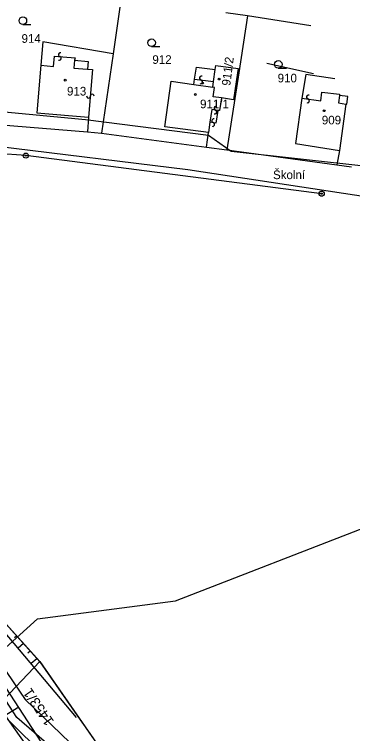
# Model space of a CAD drawing. Extents: x -469926 to -462499, y -1098642 to -1092733.
# Drawn here: x -465657.2 to -465590.7, y -1094686.3 to -1094544.8 of the extents above; entities that cross this region are included whole.
import ezdxf

# ---------------------------------------------------------------- set-up
doc = ezdxf.new("R2010")
doc.units = 0
for name, color, linetype in [('Vrstva 1', 7, 'Continuous'), ('Vrstva 10', 7, 'Continuous'), ('Vrstva 12', 7, 'Continuous'), ('Vrstva 14', 7, 'Continuous'), ('Vrstva 24', 7, 'Continuous'), ('Vrstva 25', 7, 'Continuous'), ('Vrstva 4', 7, 'Continuous'), ('Vrstva 48', 7, 'Continuous'), ('Vrstva 50', 7, 'Continuous'), ('Vrstva 51', 7, 'Continuous'), ('Vrstva 6', 7, 'Continuous'), ('Vrstva 63', 7, 'Continuous'), ('Vrstva 8', 7, 'Continuous')]:
    doc.layers.add(name, color=color, linetype=linetype)

msp = doc.modelspace()

# ---------------------------------------------------------------- linework, layer by layer
at = {"layer": 'Vrstva 1'}
for p, q in [((-465636.16, -1094541.5), (-465637.77, -1094552.57)), ((-465636.16, -1094541.5), (-465637.77, -1094552.57)), ((-465611.32, -1094545.13), (-465615.57, -1094544.51)), ((-465611.32, -1094545.13), (-465615.57, -1094544.51)), ((-465611.32, -1094545.13), (-465613.04, -1094556.33)), ((-465611.32, -1094545.13), (-465613.04, -1094556.33)), ((-465598.88, -1094547.04), (-465611.32, -1094545.13)), ((-465598.88, -1094547.04), (-465611.32, -1094545.13)), ((-465651.57, -1094550.2), (-465651.99, -1094554.83)), ((-465651.57, -1094550.2), (-465651.99, -1094554.83)), ((-465637.77, -1094552.57), (-465651.57, -1094550.2)), ((-465637.77, -1094552.57), (-465651.57, -1094550.2)), ((-465637.77, -1094552.57), (-465640.03, -1094568.16)), ((-465637.77, -1094552.57), (-465640.03, -1094568.16)), ((-465651.99, -1094554.83), (-465652.73, -1094564.21)), ((-465651.99, -1094554.83), (-465652.73, -1094564.21)), ((-465617.66, -1094555.69), (-465617.54, -1094554.85)), ((-465617.66, -1094555.69), (-465617.54, -1094554.85)), ((-465617.54, -1094554.85), (-465613.16, -1094555.49)), ((-465617.54, -1094554.85), (-465613.16, -1094555.49)), ((-465607.54, -1094554.4), (-465598.34, -1094556.44)), ((-465607.54, -1094554.4), (-465598.34, -1094556.44)), ((-465621.77, -1094557.56), (-465621.38, -1094555.18)), ((-465621.77, -1094557.56), (-465621.38, -1094555.18)), ((-465621.38, -1094555.18), (-465617.66, -1094555.69)), ((-465621.38, -1094555.18), (-465617.66, -1094555.69)), ((-465618, -1094558.02), (-465617.66, -1094555.69)), ((-465618, -1094558.02), (-465617.66, -1094555.69)), ((-465613.04, -1094556.33), (-465615.37, -1094571.49)), ((-465613.04, -1094556.33), (-465615.37, -1094571.49)), ((-465613.28, -1094556.3), (-465614.06, -1094561.65)), ((-465613.28, -1094556.3), (-465614.06, -1094561.65)), ((-465613.16, -1094555.49), (-465613.28, -1094556.3)), ((-465613.16, -1094555.49), (-465613.28, -1094556.3)), ((-465613.28, -1094556.3), (-465613.04, -1094556.33)), ((-465613.28, -1094556.3), (-465613.04, -1094556.33)), ((-465621.91, -1094558.59), (-465621.77, -1094557.56)), ((-465621.91, -1094558.59), (-465621.77, -1094557.56)), ((-465599.83, -1094556.66), (-465600.65, -1094561.28)), ((-465594.17, -1094557.49), (-465599.83, -1094556.66)), ((-465627.59, -1094566.91), (-465626.37, -1094557.95)), ((-465627.59, -1094566.91), (-465626.37, -1094557.95)), ((-465626.37, -1094557.95), (-465621.91, -1094558.59)), ((-465626.37, -1094557.95), (-465621.91, -1094558.59)), ((-465618.16, -1094559.14), (-465618, -1094558.02)), ((-465618.16, -1094559.14), (-465618, -1094558.02)), ((-465617.82, -1094559.19), (-465618.16, -1094559.14)), ((-465617.82, -1094559.19), (-465618.16, -1094559.14)), ((-465618.06, -1094561.01), (-465617.82, -1094559.19)), ((-465618.06, -1094561.01), (-465617.82, -1094559.19)), ((-465616.46, -1094561.21), (-465618.06, -1094561.01)), ((-465616.46, -1094561.21), (-465618.06, -1094561.01)), ((-465614.06, -1094561.65), (-465616.46, -1094561.21)), ((-465614.06, -1094561.65), (-465616.46, -1094561.21)), ((-465600.65, -1094561.28), (-465601.91, -1094570.19)), ((-465652.73, -1094564.21), (-465642.57, -1094565.03)), ((-465652.73, -1094564.21), (-465642.57, -1094565.03)), ((-465663.66, -1094566.23), (-465642.79, -1094567.93)), ((-465663.66, -1094566.23), (-465642.79, -1094567.93)), ((-465642.57, -1094565.03), (-465642.79, -1094567.93)), ((-465642.57, -1094565.03), (-465642.79, -1094567.93)), ((-465618.98, -1094568.05), (-465627.59, -1094566.91)), ((-465618.98, -1094568.05), (-465627.59, -1094566.91)), ((-465654.92, -1094572.6), (-465713, -1094568.41)), ((-465654.92, -1094572.6), (-465713, -1094568.41)), ((-465642.79, -1094567.93), (-465640.03, -1094568.16)), ((-465642.79, -1094567.93), (-465640.03, -1094568.16)), ((-465640.03, -1094568.16), (-465619.38, -1094570.95)), ((-465640.03, -1094568.16), (-465619.38, -1094570.95)), ((-465619.38, -1094570.95), (-465618.98, -1094568.05)), ((-465619.38, -1094570.95), (-465618.98, -1094568.05)), ((-465601.91, -1094570.19), (-465593.22, -1094571.59)), ((-465619.38, -1094570.95), (-465615.37, -1094571.49)), ((-465619.38, -1094570.95), (-465615.37, -1094571.49)), ((-465615.37, -1094571.49), (-465593.75, -1094574.44)), ((-465593.22, -1094571.59), (-465593.75, -1094574.44)), ((-465596.74, -1094580.09), (-465654.92, -1094572.6)), ((-465593.75, -1094574.44), (-465590.86, -1094574.83)), ((-465660.01, -1094663.44), (-465652.18, -1094672.09)), ((-465660.01, -1094663.44), (-465652.18, -1094672.09)), ((-465652.18, -1094672.09), (-465617.16, -1094722.6))]:
    msp.add_line(p, q, dxfattribs=at)
at = {"layer": 'Vrstva 10'}
msp.add_lwpolyline([(-465713, -1094568.41), (-465707.97, -1094574.94), (-465696.43, -1094593.1), (-465670.01, -1094647.6), (-465660.01, -1094663.44), (-465652.18, -1094672.09), (-465617.16, -1094722.6)], dxfattribs=at)
at = {"layer": 'Vrstva 12'}
for p, q in [((-465625.5, -1094660.17), (-465579.71, -1094642.44)), ((-465652.64, -1094663.73), (-465625.5, -1094660.17)), ((-465652.64, -1094663.73), (-465625.5, -1094660.17)), ((-465660.37, -1094670.68), (-465652.64, -1094663.73)), ((-465660.37, -1094670.68), (-465652.64, -1094663.73))]:
    msp.add_line(p, q, dxfattribs=at)
at = {"layer": 'Vrstva 14'}
for p, q in [((-465643.21, -1094565.55), (-465675.65, -1094562.56)), ((-465643.21, -1094565.55), (-465675.65, -1094562.56)), ((-465619.02, -1094568.67), (-465643.21, -1094565.55)), ((-465619.02, -1094568.67), (-465643.21, -1094565.55)), ((-465614.52, -1094571.79), (-465619.02, -1094568.67)), ((-465614.52, -1094571.79), (-465619.02, -1094568.67)), ((-465561.31, -1094577.68), (-465614.52, -1094571.79))]:
    msp.add_line(p, q, dxfattribs=at)
at = {"layer": 'Vrstva 24'}
for centre, radius in [((-465654.92, -1094572.6), 0.5), ((-465654.92, -1094572.6), 0.5), ((-465654.92, -1094572.6), 0.1), ((-465654.92, -1094572.6), 0.1), ((-465596.74, -1094580.09), 0.5), ((-465596.74, -1094580.09), 0.1)]:
    msp.add_circle(centre, radius, dxfattribs=at)
at = {"layer": 'Vrstva 25'}
for p, q in [((-465655.51, -1094546.81), (-465653.91, -1094546.81)), ((-465655.51, -1094546.81), (-465653.91, -1094546.81)), ((-465630.19, -1094551.14), (-465628.59, -1094551.14)), ((-465630.19, -1094551.14), (-465628.59, -1094551.14)), ((-465605.28, -1094555.41), (-465603.68, -1094555.41)), ((-465605.28, -1094555.41), (-465603.68, -1094555.41))]:
    msp.add_line(p, q, dxfattribs=at)
for centre, radius in [((-465655.51, -1094546.06), 0.75), ((-465655.51, -1094546.06), 0.75), ((-465630.19, -1094550.39), 0.75), ((-465630.19, -1094550.39), 0.75), ((-465605.28, -1094554.66), 0.75), ((-465605.28, -1094554.66), 0.75), ((-465647.17, -1094557.77), 0.175), ((-465647.17, -1094557.77), 0.175), ((-465616.9, -1094557.54), 0.175), ((-465616.9, -1094557.54), 0.175), ((-465620.15, -1094558.33), 0.175), ((-465620.15, -1094558.33), 0.175), ((-465621.59, -1094560.58), 0.175), ((-465621.59, -1094560.58), 0.175), ((-465596.24, -1094563.78), 0.175)]:
    msp.add_circle(centre, radius, dxfattribs=at)
at = {"layer": 'Vrstva 4'}
for p, q in [((-465649.48, -1094555.07), (-465649.26, -1094553.02)), ((-465649.48, -1094555.07), (-465649.26, -1094553.02)), ((-465649.26, -1094553.02), (-465645.25, -1094553.37)), ((-465649.26, -1094553.02), (-465645.25, -1094553.37)), ((-465645.25, -1094553.37), (-465645.35, -1094553.84)), ((-465645.25, -1094553.37), (-465645.35, -1094553.84)), ((-465651.99, -1094554.83), (-465649.48, -1094555.07)), ((-465651.99, -1094554.83), (-465649.48, -1094555.07)), ((-465645.35, -1094553.84), (-465645.47, -1094555.37)), ((-465645.35, -1094553.84), (-465645.47, -1094555.37)), ((-465645.35, -1094553.84), (-465642.67, -1094554.06)), ((-465645.35, -1094553.84), (-465642.67, -1094554.06)), ((-465642.67, -1094554.06), (-465642.79, -1094555.59)), ((-465642.67, -1094554.06), (-465642.79, -1094555.59)), ((-465645.47, -1094555.37), (-465642.79, -1094555.59)), ((-465645.47, -1094555.37), (-465642.79, -1094555.59)), ((-465642.79, -1094555.59), (-465641.81, -1094555.67)), ((-465642.79, -1094555.59), (-465641.81, -1094555.67)), ((-465641.81, -1094555.67), (-465642.57, -1094565.03)), ((-465641.81, -1094555.67), (-465642.57, -1094565.03)), ((-465621.77, -1094557.56), (-465618, -1094558.02)), ((-465621.77, -1094557.56), (-465618, -1094558.02)), ((-465621.91, -1094558.59), (-465618.16, -1094559.14)), ((-465621.91, -1094558.59), (-465618.16, -1094559.14)), ((-465596.93, -1094561.82), (-465596.71, -1094560.09)), ((-465596.71, -1094560.09), (-465593.23, -1094560.53)), ((-465593.23, -1094560.53), (-465593.26, -1094560.79)), ((-465616.46, -1094561.21), (-465616.85, -1094563.73)), ((-465616.46, -1094561.21), (-465616.85, -1094563.73)), ((-465600.65, -1094561.28), (-465596.93, -1094561.82)), ((-465593.26, -1094560.79), (-465593.46, -1094562.25)), ((-465591.61, -1094561), (-465593.26, -1094560.79)), ((-465591.81, -1094562.5), (-465591.61, -1094561)), ((-465593.46, -1094562.25), (-465591.98, -1094562.51)), ((-465591.98, -1094562.51), (-465593.22, -1094571.59)), ((-465591.98, -1094562.51), (-465591.81, -1094562.5)), ((-465618.37, -1094563.55), (-465618.71, -1094566.03)), ((-465618.37, -1094563.55), (-465618.71, -1094566.03)), ((-465617.19, -1094563.71), (-465618.37, -1094563.55)), ((-465617.19, -1094563.71), (-465618.37, -1094563.55)), ((-465617.19, -1094563.71), (-465617.53, -1094566.19)), ((-465617.19, -1094563.71), (-465617.53, -1094566.19)), ((-465616.85, -1094563.73), (-465617.19, -1094563.71)), ((-465616.85, -1094563.73), (-465617.19, -1094563.71)), ((-465618.71, -1094566.03), (-465618.98, -1094568.05)), ((-465618.71, -1094566.03), (-465618.98, -1094568.05)), ((-465617.53, -1094566.19), (-465618.71, -1094566.03)), ((-465617.53, -1094566.19), (-465618.71, -1094566.03)), ((-465670.79, -1094691.66), (-465652.18, -1094672.09)), ((-465670.79, -1094691.66), (-465652.18, -1094672.09))]:
    msp.add_line(p, q, dxfattribs=at)
at = {"layer": 'Vrstva 48'}
for points in [[(-465656.72, -1094667.08), (-465657.17, -1094667.49)], [(-465656.72, -1094667.08), (-465657.17, -1094667.49)], [(-465655.39, -1094668.58), (-465656.43, -1094669.5)], [(-465655.39, -1094668.58), (-465656.43, -1094669.5)], [(-465654.06, -1094670.07), (-465654.54, -1094670.5)], [(-465654.06, -1094670.07), (-465654.54, -1094670.5)], [(-465652.74, -1094671.57), (-465653.85, -1094672.54)], [(-465652.74, -1094671.57), (-465653.85, -1094672.54)], [(-465659.48, -1094683), (-465656.33, -1094681.02)], [(-465659.48, -1094683), (-465656.33, -1094681.02)]]:
    msp.add_lwpolyline(points, dxfattribs=at)
at = {"layer": 'Vrstva 51'}
for centre, radius, start, end in [((-465648.15, -1094552.74), 0.376, 68.9904, 255.3015), ((-465648.15, -1094552.74), 0.376, 68.9904, 255.3015), ((-465648.34, -1094553.47), 0.377, 248.3143, 75.9775), ((-465648.34, -1094553.47), 0.377, 248.3143, 75.9775), ((-465620.38, -1094557.35), 0.376, 68.9904, 255.3015), ((-465620.38, -1094557.35), 0.376, 68.9904, 255.3015), ((-465620.56, -1094558.08), 0.377, 248.3143, 75.9775), ((-465620.56, -1094558.08), 0.377, 248.3143, 75.9775), ((-465641.86, -1094560.89), 0.376, 354.7104, 181.0215), ((-465641.86, -1094560.89), 0.376, 354.7104, 181.0215), ((-465642.61, -1094560.9), 0.377, 174.0343, 1.6975), ((-465642.61, -1094560.9), 0.377, 174.0343, 1.6975), ((-465599.35, -1094561.09), 0.376, 68.9904, 255.3015), ((-465599.53, -1094561.82), 0.377, 248.3143, 75.9775), ((-465617.55, -1094563.28), 0.376, 68.9904, 255.3015), ((-465617.55, -1094563.28), 0.376, 68.9904, 255.3015), ((-465617.74, -1094564.01), 0.377, 248.3143, 75.9775), ((-465617.74, -1094564.01), 0.377, 248.3143, 75.9775), ((-465617.99, -1094565.75), 0.376, 68.9904, 255.3015), ((-465617.99, -1094565.75), 0.376, 68.9904, 255.3015), ((-465618.17, -1094566.48), 0.377, 248.3143, 75.9775), ((-465618.17, -1094566.48), 0.377, 248.3143, 75.9775)]:
    msp.add_arc(centre, radius, start, end, dxfattribs=at)
at = {"layer": 'Vrstva 6'}
for points in [[(-465764.57, -1094524.1), (-465744.54, -1094553.15), (-465728.17, -1094576.48), (-465711.62, -1094600.56), (-465689.57, -1094631.93), (-465682.97, -1094643.74), (-465676.37, -1094655.54), (-465658.45, -1094683.55), (-465643.77, -1094704.26), (-465629.83, -1094723.97), (-465615.89, -1094743.67), (-465598.7, -1094758.84), (-465586.6, -1094780.28), (-465568.25, -1094802.77), (-465557.01, -1094824.5), (-465549.26, -1094833.47), (-465549.2, -1094829.81)], [(-465711.62, -1094600.56), (-465688.58, -1094629.09), (-465673.68, -1094652.27), (-465655.08, -1094679.58), (-465632.16, -1094701.61), (-465626.96, -1094703.6)], [(-465628.68, -1094705.89), (-465635.69, -1094701.33), (-465656.72, -1094683.11), (-465675.29, -1094654.47), (-465681.87, -1094645.7)], [(-465658.45, -1094683.55), (-465636.49, -1094705.33), (-465630.25, -1094708.75)]]:
    msp.add_lwpolyline(points, dxfattribs=at)
at = {"layer": 'Vrstva 63'}
for points in [[(-465643.79, -1094700.32), (-465644.09, -1094699.91), (-465689.14, -1094630.72)], [(-465644.93, -1094683.17), (-465689.14, -1094630.72)], [(-465643.79, -1094700.32), (-465644.09, -1094699.91), (-465689.14, -1094630.72)], [(-465644.93, -1094683.17), (-465689.14, -1094630.72)], [(-465660, -1094663.46), (-465652.18, -1094672.2)], [(-465660, -1094663.46), (-465652.18, -1094672.2)], [(-465652.18, -1094672.2), (-465643.79, -1094684.28)], [(-465652.18, -1094672.2), (-465643.79, -1094684.28)]]:
    msp.add_lwpolyline(points, dxfattribs=at)
at = {"layer": 'Vrstva 8'}
for p, q in [((-465623.08, -1094575.43), (-465672.04, -1094569.38)), ((-465623.08, -1094575.43), (-465672.04, -1094569.38)), ((-465538.56, -1094588.22), (-465623.08, -1094575.43))]:
    msp.add_line(p, q, dxfattribs=at)

# ---------------------------------------------------------------- texts
at = {"layer": 'Vrstva 50'}
for s, p in [('914', (-465655.77, -1094550.41)), ('912', (-465630.04, -1094554.56)), ('910', (-465605.4, -1094558.2)), ('913', (-465646.83, -1094560.78)), ('911/1', (-465620.66, -1094563.29)), ('909', (-465596.71, -1094566.46)), ('Školní', (-465606.31, -1094577.23))]:
    msp.add_text(s, height=1.7, dxfattribs=at).set_placement(p)
msp.add_text('911/2', height=1.7, rotation=82.791, dxfattribs=at).set_placement((-465614.73, -1094558.94))
msp.add_text('911/2', height=1.7, rotation=82.791, dxfattribs=at).set_placement((-465614.73, -1094558.94))
at = {"layer": 'Vrstva 63'}
msp.add_text('1453/1', height=2, rotation=124.506, dxfattribs=at).set_placement((-465649.3, -1094683.89))
msp.add_text('1453/1', height=2, rotation=124.506, dxfattribs=at).set_placement((-465649.3, -1094683.89))

doc.saveas('drawing.dxf')
